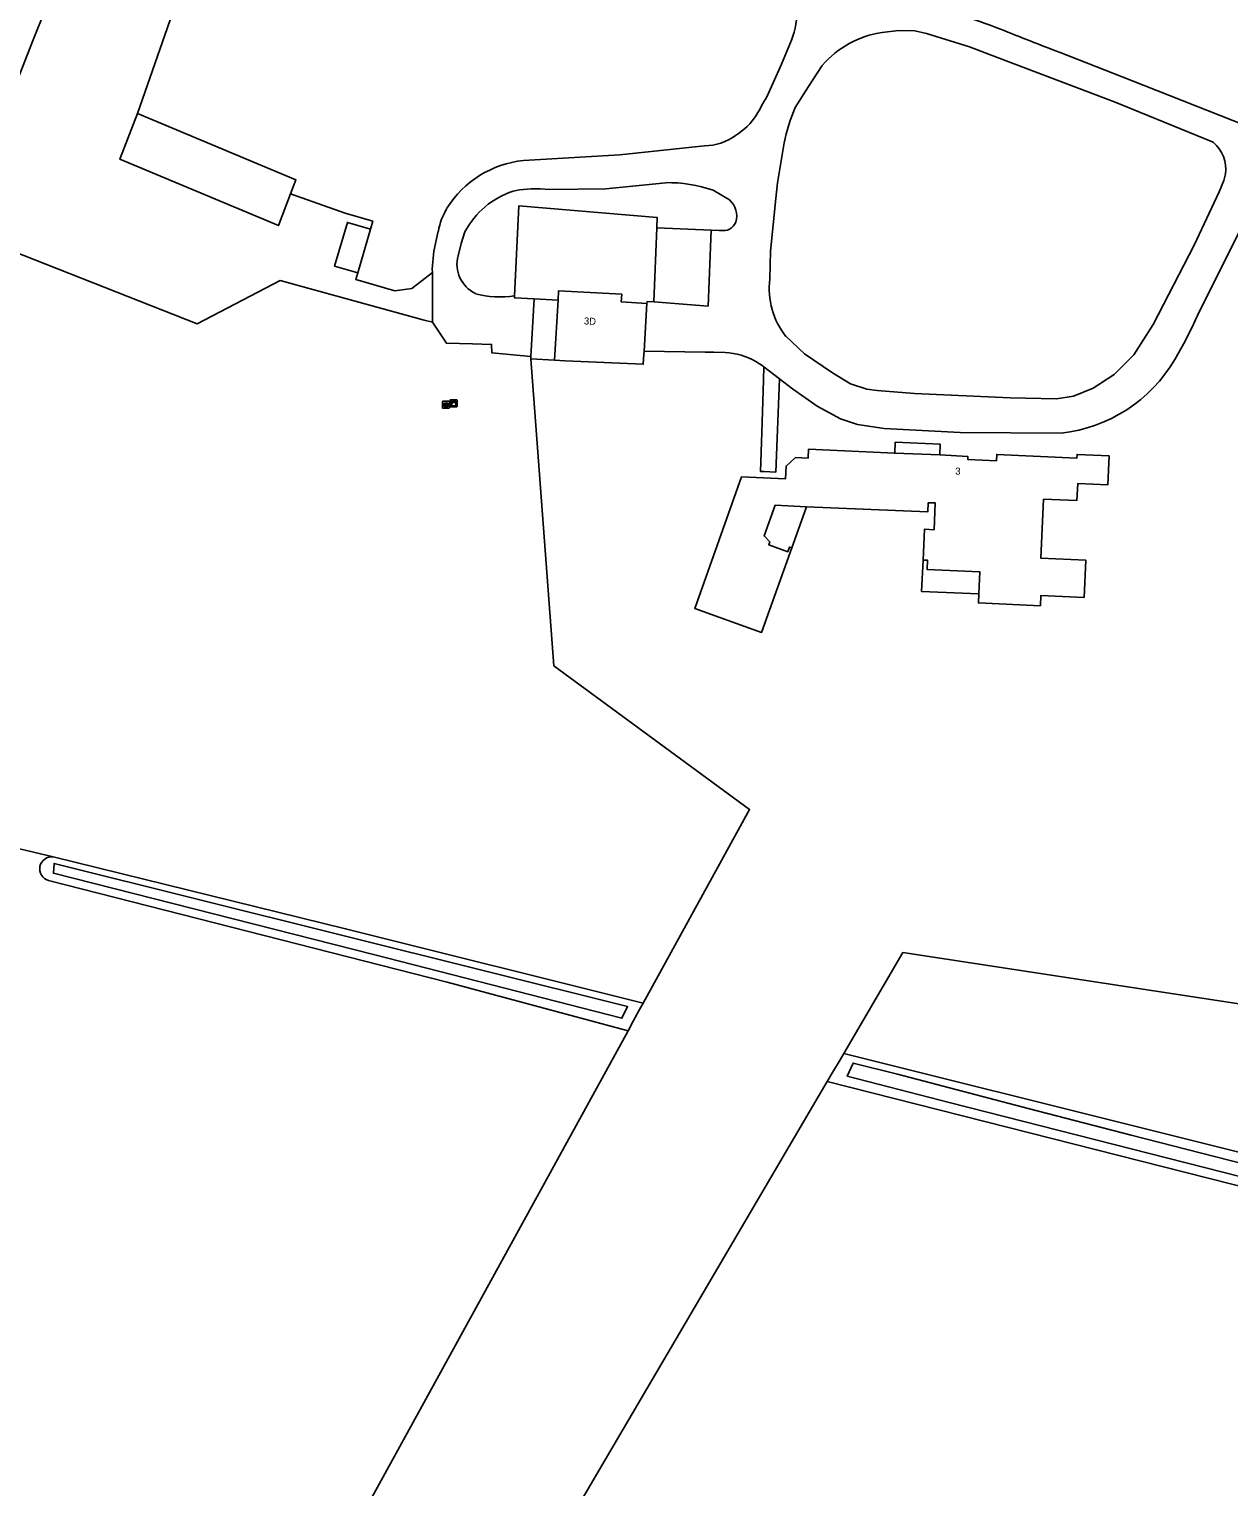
# Model space of a CAD drawing. Extents: x 156502 to 159075, y 384229 to 386100.
# Drawn here: x 158041.4 to 158212, y 384870.4 to 385077.7 of the extents above; entities that cross this region are included whole.
import ezdxf

# ---------------------------------------------------------------- set-up
doc = ezdxf.new("R2010")
doc.units = 0
for name, color, linetype in [('IMGEO_Erf', 7, 'Continuous'), ('IMGEO_Gemengd_bos', 7, 'Continuous'), ('IMGEO_Groenvoorziening', 7, 'Continuous'), ('IMGEO_Kast', 7, 'Continuous'), ('IMGEO_Oever', 7, 'Continuous'), ('IMGEO_Pand', 7, 'Continuous'), ('IMGEO_Pand_nummerreeks', 7, 'Continuous'), ('IMGEO_Pand_overbouw', 7, 'Continuous'), ('IMGEO_Parkeervlak_gesloten', 7, 'Continuous'), ('IMGEO_Rijbaan_lokaal_gesloten', 7, 'Continuous'), ('IMGEO_Rioolput', 7, 'Continuous'), ('IMGEO_Voetpad_onverhard', 7, 'Continuous'), ('IMGEO_Waterloop', 7, 'Continuous')]:
    doc.layers.add(name, color=color, linetype=linetype)

msp = doc.modelspace()

# ---------------------------------------------------------------- linework, layer by layer
at = {"layer": 'IMGEO_Erf'}
msp.add_lwpolyline([(158130.68, 385049.46), (158130.74, 385050.93), (158111.07, 385052.6), (158110.45, 385039.8), (158110.43, 385039.52), (158113.23, 385039.37), (158116.63, 385039.17), (158116.71, 385040.53), (158125.68, 385040.02), (158125.61, 385038.93), (158129.25, 385038.72), (158129.29, 385038.99), (158130.25, 385038.96)], close=True, dxfattribs=at)
at = {"layer": 'IMGEO_Gemengd_bos'}
for points in [[(158033.69, 385055.05), (158042.02, 385076.22), (158043.74, 385080.59), (158047.49, 385090.13), (158063.22, 385084.15), (158056.81, 385065.74), (158079.36, 385056.3), (158078.61, 385054.32), (158086.38, 385051.55), (158090.29, 385050.4), (158089.96, 385049.28), (158088.14, 385043.06), (158087.87, 385042.14), (158093.44, 385040.5), (158095.84, 385040.85), (158098.76, 385043.1), (158098.75, 385043.6), (158098.96, 385046.17), (158099.6, 385049.02)], [(158146.31, 385068.11), (158147.22, 385070.08), (158148.38, 385072.74), (158149.8, 385076.15)], [(158188.02, 385074.39), (158198.17, 385070.41), (158214.38, 385064.01), (158216.95, 385062.2), (158306.9, 385025.96), (158370.58, 385000), (158387.87, 384992.95)], [(158111.7, 385059.04), (158125.41, 385059.86), (158137.47, 385061.13)], [(158039.24, 384961.34), (158044.85, 384960), (158086.42, 384949.78), (158128.74, 384939.19), (158143.87, 384966.74), (158116.03, 384987.18), (158112.74, 385030.84), (158112.76, 385031.15), (158107.19, 385031.71), (158107.18, 385032.88), (158104.47, 385032.95), (158100.75, 385033.05), (158098.78, 385036.03), (158097.57, 385036.36), (158077.13, 385041.96), (158065.33, 385035.82), (158032.33, 385048.8)], [(158044.85, 384960), (158039.24, 384961.34)], [(158126.59, 384935.27), (158100.88, 384942.2), (158044.17, 384956.66)], [(158327.33, 384873.03), (158330.05, 384877.58), (158342.95, 384899.96), (158353.53, 384917.71), (158350.04, 384918.24), (158339.53, 384900.83), (158339.29, 384900.43), (158338.99, 384900.27), (158338.62, 384900.45), (158338.56, 384900.87), (158338.74, 384901.31), (158349.05, 384918.4), (158165.66, 384946.38), (158157.25, 384932.05), (158243.06, 384910.59), (158287.1, 384899.3), (158326.96, 384888.71), (158329.39, 384887.94)], [(158003.5, 384732.93), (158035.11, 384768.65), (158069.78, 384831.8), (158071.43, 384834.81), (158126.59, 384935.27)], [(158329.89, 384884.1), (158317.22, 384886.76), (158306.67, 384889.36), (158264.56, 384900.4), (158248.46, 384904.15), (158225.15, 384910.22), (158154.91, 384928.06), (158096.39, 384828.33), (158102.05, 384826.88), (158102.21, 384826.84), (158226.61, 384795.1), (158247.13, 384790.01), (158268.26, 384784.48)]]:
    msp.add_lwpolyline(points, dxfattribs=at)
for centre, radius, start, end in [((158139.92, 385080.19), 10.68, 337.7815, 3.4013), ((158159.52, 385028.6), 53.04, 67.851, 74.5481), ((158482.86, 385836.61), 817.26, 248.21267, 248.85308), ((158227.98, 385020.22), 94.67, 149.6116, 151.4029), ((158136.57, 385070.99), 9.92, 302.2145, 326.6471), ((158137.22, 385069.2), 8.08, 271.7889, 305.0575), ((158113.21, 385044.53), 14.59, 95.9317, 148.0469), ((158108.83, 385047.36), 9.37, 148.5861, 169.8084), ((158044.64, 384958.3), 1.71, 82.9909, 253.9412)]:
    msp.add_arc(centre, radius, start, end, dxfattribs=at)
at = {"layer": 'IMGEO_Groenvoorziening'}
for points in [[(158209.76, 385061.65), (158195.85, 385067.34), (158178.98, 385073.76), (158175.13, 385075.22), (158169.02, 385077.12), (158167.35, 385077.51), (158165.05, 385077.52), (158162.72, 385077.23)], [(158154.19, 385072.55), (158152.25, 385069.57), (158150.36, 385066.58)], [(158148.77, 385061.55), (158147.82, 385055.86), (158147.6, 385053.64), (158146.84, 385046.16), (158146.73, 385042.17)], [(158149.01, 385034.04), (158151.65, 385031.54), (158155.67, 385028.84), (158158.2, 385027.27), (158160.51, 385026.51), (158162.02, 385026.32), (158167.3, 385025.9), (158180.93, 385025.28), (158187.48, 385025.17), (158189.93, 385025.51), (158192.69, 385026.67), (158195.69, 385028.61), (158198.5, 385031.4), (158201.25, 385035.74), (158207.08, 385047.02), (158210.62, 385054.58), (158210.97, 385055.38), (158211.28, 385056.19), (158211.55, 385057.13)], [(158131.93, 385055.89), (158123.4, 385055.03), (158115.43, 385054.94), (158114.12, 385055.01), (158112.82, 385055.02), (158111.13, 385054.87), (158110.24, 385054.68)], [(158141, 385053.46), (158138.69, 385054.81)], [(158216.16, 385054.27), (158207.79, 385037.5), (158206.73, 385035.25), (158205.6, 385033.02), (158204.31, 385030.75)], [(158110.45, 385039.8), (158111.07, 385052.6), (158130.74, 385050.93), (158130.68, 385049.46), (158138.4, 385049.14), (158139.55, 385049.1), (158139.98, 385049.07), (158140.39, 385049.08)], [(158141.53, 385049.72), (158141.7, 385049.94), (158141.93, 385050.28)], [(158103.39, 385048.89), (158102.86, 385047.24), (158102.41, 385045.51)], [(158140.41, 385031.73), (158138.79, 385031.79), (158137.55, 385031.78), (158128.86, 385031.91), (158128.83, 385031.49), (158128.75, 385030.06), (158117.66, 385030.55), (158116.14, 385030.64), (158116.63, 385039.17), (158113.23, 385039.37), (158112.76, 385031.15), (158112.74, 385030.84), (158116.03, 384987.18), (158143.87, 384966.74), (158128.74, 384939.19), (158128.23, 384938.27), (158127.33, 384936.62), (158126.59, 384935.27), (158071.43, 384834.81), (158069.78, 384831.8), (158035.11, 384768.65), (158003.5, 384732.93)], [(158188.17, 385020.27), (158173.81, 385020.36), (158162.98, 385020.92), (158159.22, 385021.5), (158156.81, 385022.31), (158153.47, 385024.12), (158149.98, 385026.59), (158148.12, 385028.01), (158147.58, 385014.74), (158145.93, 385014.81), (158145.39, 385014.83), (158145.62, 385020.37), (158145.83, 385027.81), (158145.88, 385029.72), (158145.79, 385029.78), (158144.75, 385030.46)], [(158154.91, 384928.06), (158155.66, 384929.34), (158156.72, 384931.15), (158157.25, 384932.05), (158165.66, 384946.38), (158349.05, 384918.4), (158381.85, 384972.74), (158382.35, 384973.56)], [(158046.36, 384710.94), (158069.69, 384782.82), (158094.68, 384825.42), (158096.39, 384828.33), (158154.91, 384928.06)]]:
    msp.add_lwpolyline(points, dxfattribs=at)
msp.add_lwpolyline([(158136.07, 384995.32), (158142.71, 385014.04), (158148.97, 385013.78), (158149.06, 385015.59), (158150.38, 385016.79), (158152.17, 385016.73), (158152.23, 385017.97), (158164.51, 385017.4), (158170.93, 385017.17), (158174.9, 385016.94), (158174.88, 385016.54), (158178.95, 385016.35), (158179, 385017.25), (158190.4, 385016.71), (158190.43, 385017.25), (158194.97, 385017.04), (158194.78, 385012.9), (158190.51, 385013.1), (158190.4, 385010.69), (158185.67, 385010.9), (158185.29, 385002.48), (158191.66, 385002.19), (158191.42, 384996.88), (158185.27, 384997.16), (158185.21, 384995.71), (158176.4, 384996.11), (158176.46, 384997.39), (158176.6, 385000.53), (158169.12, 385000.87), (158169.18, 385002.19), (158168.53, 385002.22), (158168.73, 385006.59), (158170.1, 385006.53), (158170.27, 385010.34), (158169.27, 385010.38), (158169.21, 385009.09), (158151.97, 385009.79), (158147.49, 385010.01), (158145.92, 385005.66), (158146.74, 385004.83), (158146.58, 385004.38), (158149.29, 385003.41), (158149.53, 385004.07), (158149.88, 385003.95), (158145.57, 384991.92)], close=True, dxfattribs=at)
for centre, radius, start, end in [((158164.56, 385063.75), 13.61, 97.7663, 139.7016), ((158175.83, 385055.77), 27.67, 157.0109, 167.9586), ((158206.58, 385057.77), 5.01, 352.6092, 50.6216), ((158113.92, 385043.39), 11.88, 108.0707, 152.4223), ((158132.28, 385036.42), 19.48, 70.7938, 91.0277), ((158138.97, 385051.14), 3.08, 343.7315, 48.7723), ((158140.27, 385050.63), 1.56, 274.2809, 323.9475), ((158106.96, 385044.32), 4.7, 165.3599, 243.627), ((158157.73, 385040.87), 11.08, 173.2419, 218.0995), ((158108.37, 385053.01), 13.37, 254.8361, 278.9431), ((158140.01, 385022.39), 9.35, 59.5818, 87.549), ((158185.81, 385041.58), 21.44, 276.3262, 329.6768)]:
    msp.add_arc(centre, radius, start, end, dxfattribs=at)
at = {"layer": 'IMGEO_Kast'}
for p, q in [((158101.28, 385024.09), (158101.28, 385024.93)), ((158101.28, 385024.93), (158101.28, 385024.09)), ((158101.35, 385025.02), (158102.2, 385025.02)), ((158102.2, 385025.02), (158101.35, 385025.02)), ((158102.21, 385024.02), (158101.36, 385024.02)), ((158101.36, 385024.02), (158102.21, 385024.02)), ((158102.28, 385024.94), (158102.28, 385024.1)), ((158102.28, 385024.1), (158102.28, 385024.94))]:
    msp.add_line(p, q, dxfattribs=at)
for points in [[(158101.48, 385024.81), (158102.08, 385024.81), (158102.08, 385024.72), (158101.48, 385024.72), (158101.48, 385024.81)], [(158101.48, 385024.63), (158102.08, 385024.63), (158102.08, 385024.14), (158101.48, 385024.14), (158101.48, 385024.63)]]:
    msp.add_lwpolyline(points, dxfattribs=at)
msp.add_circle((158101.56, 385024.48), 0.0377, dxfattribs=at)
for centre, start, end in [((158101.36, 385024.94), 92.4484, 184.2845), ((158101.36, 385024.94), 92.4484, 184.2845), ((158101.36, 385024.1), 182.4484, 274.2845), ((158101.36, 385024.1), 182.4484, 274.2845), ((158102.2, 385024.94), 2.4484, 94.2845), ((158102.2, 385024.94), 2.4484, 94.2845), ((158102.2, 385024.1), 272.4484, 4.2845), ((158102.2, 385024.1), 272.4484, 4.2845)]:
    msp.add_arc(centre, 0.0779, start, end, dxfattribs=at)
at = {"layer": 'IMGEO_Oever'}
for points in [[(158086.42, 384949.78), (158044.85, 384960)], [(158044.17, 384956.66), (158100.88, 384942.2), (158126.59, 384935.27), (158127.33, 384936.62), (158128.23, 384938.27), (158128.74, 384939.19), (158086.42, 384949.78)], [(158329.39, 384887.94), (158326.96, 384888.71), (158287.1, 384899.3), (158243.06, 384910.59), (158157.25, 384932.05), (158156.72, 384931.15), (158155.66, 384929.34), (158154.91, 384928.06), (158225.15, 384910.22), (158248.46, 384904.15), (158264.56, 384900.4), (158306.67, 384889.36), (158317.22, 384886.76), (158329.89, 384884.1)]]:
    msp.add_lwpolyline(points, dxfattribs=at)
for points in [[(158126.51, 384938.7), (158125.72, 384937.04), (158090.38, 384946.13), (158044.88, 384957.66), (158044.97, 384959.08)], [(158329.1, 384885.67), (158328.78, 384885.46), (158328.16, 384885.41), (158326.59, 384885.73), (158318.91, 384887.72), (158172.42, 384925.02), (158157.74, 384928.8), (158158.6, 384930.67), (158164.9, 384929.1), (158183.49, 384924.23), (158198.1, 384920.41), (158328.29, 384887.11), (158328.86, 384886.59), (158329.18, 384886.17)]]:
    msp.add_lwpolyline(points, close=True, dxfattribs=at)
msp.add_arc((158044.64, 384958.3), 1.71, 82.9909, 253.9412, dxfattribs=at)
at = {"layer": 'IMGEO_Pand'}
for points in [[(158056.81, 385065.74), (158054.33, 385059.22), (158076.88, 385049.78), (158078.61, 385054.32), (158079.36, 385056.3)], [(158089.96, 385049.28), (158086.67, 385050.25), (158084.85, 385044.03), (158088.14, 385043.06)], [(158129.25, 385038.72), (158125.61, 385038.93), (158125.68, 385040.02), (158116.71, 385040.53), (158116.63, 385039.17), (158116.14, 385030.64), (158117.66, 385030.55), (158128.75, 385030.06), (158128.83, 385031.49), (158128.86, 385031.91)], [(158142.71, 385014.04), (158136.07, 384995.32), (158145.57, 384991.92), (158149.88, 385003.95), (158149.53, 385004.07), (158149.29, 385003.41), (158146.58, 385004.38), (158146.74, 385004.83), (158145.92, 385005.66), (158147.49, 385010.01), (158151.97, 385009.79), (158169.21, 385009.09), (158169.27, 385010.38), (158170.27, 385010.34), (158170.1, 385006.53), (158168.73, 385006.59), (158168.53, 385002.22), (158169.18, 385002.19), (158169.12, 385000.87), (158176.6, 385000.53), (158176.46, 384997.39), (158176.4, 384996.11), (158185.21, 384995.71), (158185.27, 384997.16), (158191.42, 384996.88), (158191.66, 385002.19), (158185.29, 385002.48), (158185.67, 385010.9), (158190.4, 385010.69), (158190.51, 385013.1), (158194.78, 385012.9), (158194.97, 385017.04), (158190.43, 385017.25), (158190.4, 385016.71), (158179, 385017.25), (158178.95, 385016.35), (158174.88, 385016.54), (158174.9, 385016.94), (158170.93, 385017.17), (158164.51, 385017.4), (158152.23, 385017.97), (158152.17, 385016.73), (158150.38, 385016.79), (158149.06, 385015.59), (158148.97, 385013.78)]]:
    msp.add_lwpolyline(points, close=True, dxfattribs=at)
at = {"layer": 'IMGEO_Pand_overbouw'}
for points in [[(158116.63, 385039.17), (158113.23, 385039.37), (158112.76, 385031.15), (158112.74, 385030.84), (158116.14, 385030.64)], [(158170.93, 385017.17), (158170.98, 385018.68), (158164.57, 385018.98), (158164.51, 385017.4)], [(158151.97, 385009.79), (158147.49, 385010.01), (158145.92, 385005.66), (158146.74, 385004.83), (158146.58, 385004.38), (158149.29, 385003.41), (158149.53, 385004.07), (158149.88, 385003.95)], [(158176.46, 384997.39), (158176.6, 385000.53), (158169.12, 385000.87), (158169.18, 385002.19), (158168.53, 385002.22), (158168.32, 384997.76)]]:
    msp.add_lwpolyline(points, close=True, dxfattribs=at)
at = {"layer": 'IMGEO_Parkeervlak_gesloten'}
msp.add_lwpolyline([(158138.4, 385049.14), (158130.68, 385049.46), (158130.25, 385038.96), (158137.96, 385038.33)], close=True, dxfattribs=at)
at = {"layer": 'IMGEO_Rijbaan_lokaal_gesloten'}
for points in [[(158032.33, 385048.8), (158065.33, 385035.82), (158077.13, 385041.96), (158097.57, 385036.36), (158098.78, 385036.03), (158098.76, 385041.03), (158098.76, 385043.1), (158095.84, 385040.85), (158093.44, 385040.5), (158087.87, 385042.14), (158088.14, 385043.06), (158084.85, 385044.03), (158086.67, 385050.25), (158089.96, 385049.28), (158090.29, 385050.4), (158086.38, 385051.55), (158078.61, 385054.32), (158076.88, 385049.78), (158054.33, 385059.22), (158056.81, 385065.74), (158063.22, 385084.15)], [(158043.74, 385080.59), (158042.02, 385076.22), (158033.69, 385055.05)], [(158162.72, 385077.23), (158165.05, 385077.52), (158167.35, 385077.51), (158169.02, 385077.12), (158175.13, 385075.22), (158178.98, 385073.76), (158195.85, 385067.34), (158209.76, 385061.65)], [(158149.8, 385076.15), (158148.38, 385072.74), (158147.22, 385070.08), (158146.31, 385068.11)], [(158387.87, 384992.95), (158370.58, 385000), (158306.9, 385025.96), (158216.95, 385062.2), (158214.38, 385064.01), (158198.17, 385070.41), (158188.02, 385074.39)], [(158150.36, 385066.58), (158152.25, 385069.57), (158154.19, 385072.55)], [(158137.47, 385061.13), (158125.41, 385059.86), (158111.7, 385059.04)], [(158146.73, 385042.17), (158146.84, 385046.16), (158147.6, 385053.64), (158147.82, 385055.86), (158148.77, 385061.55)], [(158211.55, 385057.13), (158211.28, 385056.19), (158210.97, 385055.38), (158210.62, 385054.58), (158207.08, 385047.02), (158201.25, 385035.74), (158198.5, 385031.4), (158195.69, 385028.61), (158192.69, 385026.67), (158189.93, 385025.51), (158187.48, 385025.17), (158180.93, 385025.28), (158167.3, 385025.9), (158162.02, 385026.32), (158160.51, 385026.51), (158158.2, 385027.27), (158155.67, 385028.84), (158151.65, 385031.54), (158149.01, 385034.04)], [(158110.24, 385054.68), (158111.13, 385054.87), (158112.82, 385055.02), (158114.12, 385055.01), (158115.43, 385054.94), (158123.4, 385055.03), (158131.93, 385055.89)], [(158138.69, 385054.81), (158141, 385053.46)], [(158204.31, 385030.75), (158205.6, 385033.02), (158206.73, 385035.25), (158207.79, 385037.5), (158216.16, 385054.27)], [(158141.93, 385050.28), (158141.7, 385049.94), (158141.53, 385049.72)], [(158099.6, 385049.02), (158098.96, 385046.17), (158098.75, 385043.6), (158098.76, 385043.1), (158098.76, 385041.03), (158098.78, 385036.03), (158100.75, 385033.05), (158104.47, 385032.95), (158107.18, 385032.88), (158107.19, 385031.71), (158112.76, 385031.15), (158113.23, 385039.37), (158110.43, 385039.52), (158110.45, 385039.8)], [(158102.41, 385045.51), (158102.86, 385047.24), (158103.39, 385048.89)], [(158140.39, 385049.08), (158139.98, 385049.07), (158139.55, 385049.1), (158138.4, 385049.14), (158137.96, 385038.33), (158130.25, 385038.96), (158129.29, 385038.99), (158129.25, 385038.72), (158128.86, 385031.91), (158137.55, 385031.78), (158138.79, 385031.79), (158140.41, 385031.73)], [(158144.75, 385030.46), (158145.79, 385029.78), (158145.88, 385029.72), (158148.12, 385028.01), (158149.98, 385026.59), (158153.47, 385024.12), (158156.81, 385022.31), (158159.22, 385021.5), (158162.98, 385020.92), (158173.81, 385020.36), (158188.17, 385020.27)]]:
    msp.add_lwpolyline(points, dxfattribs=at)
for centre, radius, start, end in [((158139.92, 385080.19), 10.68, 337.7815, 3.4013), ((158159.52, 385028.6), 53.04, 67.851, 74.5481), ((158164.56, 385063.75), 13.61, 97.7663, 139.7016), ((158482.86, 385836.61), 817.26, 248.21267, 248.85308), ((158227.98, 385020.22), 94.67, 149.6116, 151.4029), ((158136.57, 385070.99), 9.92, 302.2145, 326.6471), ((158175.83, 385055.77), 27.67, 157.0109, 167.9586), ((158137.22, 385069.2), 8.08, 271.7889, 305.0575), ((158206.58, 385057.77), 5.01, 352.6092, 50.6216), ((158113.21, 385044.53), 14.59, 95.9317, 148.0469), ((158113.92, 385043.39), 11.88, 108.0707, 152.4223), ((158132.28, 385036.42), 19.48, 70.7938, 91.0277), ((158108.83, 385047.36), 9.37, 148.5861, 169.8084), ((158138.97, 385051.14), 3.08, 343.7315, 48.7723), ((158140.27, 385050.63), 1.56, 274.2809, 323.9475), ((158106.96, 385044.32), 4.7, 165.3599, 243.627), ((158157.73, 385040.87), 11.08, 173.2419, 218.0995), ((158108.37, 385053.01), 13.37, 254.8361, 278.9431), ((158140.01, 385022.39), 9.35, 59.5818, 87.549), ((158185.81, 385041.58), 21.44, 276.3262, 329.6768)]:
    msp.add_arc(centre, radius, start, end, dxfattribs=at)
at = {"layer": 'IMGEO_Rioolput'}
for p, q in [((158100.19, 385023.88), (158100.19, 385024.73)), ((158100.26, 385024.81), (158101.11, 385024.81)), ((158101.11, 385023.81), (158100.26, 385023.81)), ((158100.45, 385024.3), (158100.45, 385024.31)), ((158100.49, 385024.35), (158100.89, 385024.35)), ((158100.88, 385024.26), (158100.49, 385024.26)), ((158100.7, 385024.03), (158100.67, 385024.03)), ((158100.68, 385024.59), (158100.7, 385024.59)), ((158100.93, 385024.31), (158100.93, 385024.3)), ((158101.19, 385024.73), (158101.19, 385023.88))]:
    msp.add_line(p, q, dxfattribs=at)
for points in [[(158100.19, 385023.88), (158100.19, 385024.73)], [(158100.26, 385024.81), (158101.11, 385024.81)], [(158101.11, 385023.81), (158100.26, 385023.81)], [(158101.19, 385024.73), (158101.19, 385023.88)]]:
    msp.add_lwpolyline(points, dxfattribs=at)
for centre, radius, start, end in [((158100.26, 385024.73), 0.0765, 91.552, 178.448), ((158100.26, 385024.73), 0.0765, 91.552, 178.448), ((158100.26, 385023.88), 0.0765, 181.552, 268.448), ((158100.26, 385023.88), 0.0765, 181.552, 268.448), ((158100.49, 385024.31), 0.0403, 85.8775, 175.7526), ((158100.48, 385024.3), 0.0366, 178.938, 274.7102), ((158100.89, 385024.31), 0.043, 264.8664, 352.4533), ((158100.89, 385024.31), 0.0386, 1.7309, 96.639), ((158101.11, 385024.73), 0.0765, 1.552, 88.448), ((158101.11, 385024.73), 0.0765, 1.552, 88.448), ((158101.11, 385023.88), 0.0765, 271.552, 358.448), ((158101.11, 385023.88), 0.0765, 271.552, 358.448)]:
    msp.add_arc(centre, radius, start, end, dxfattribs=at)
for centre, major_axis, ratio, start_param, end_param in [((158100.67, 385024.31), (-0.387, 0.002), 0.722429, 4.712389, 7.853982), ((158100.7, 385024.31), (-0.39, 0.002), 0.717154, 1.570796, 4.712389)]:
    msp.add_ellipse(centre, major_axis=major_axis, ratio=ratio, start_param=start_param, end_param=end_param, dxfattribs=at)
at = {"layer": 'IMGEO_Voetpad_onverhard'}
msp.add_lwpolyline([(158148.12, 385028.01), (158145.88, 385029.72), (158145.83, 385027.81), (158145.62, 385020.37), (158145.39, 385014.83), (158145.93, 385014.81), (158147.58, 385014.74)], close=True, dxfattribs=at)
at = {"layer": 'IMGEO_Waterloop'}
for points in [[(158044.97, 384959.08), (158044.88, 384957.66), (158090.38, 384946.13), (158125.72, 384937.04), (158126.51, 384938.7)], [(158183.49, 384924.23), (158164.9, 384929.1), (158158.6, 384930.67), (158157.74, 384928.8), (158172.42, 384925.02), (158318.91, 384887.72), (158326.59, 384885.73), (158328.16, 384885.41), (158328.78, 384885.46), (158329.1, 384885.67), (158329.18, 384886.17), (158328.86, 384886.59), (158328.29, 384887.11), (158198.1, 384920.41)]]:
    msp.add_lwpolyline(points, close=True, dxfattribs=at)

# ---------------------------------------------------------------- texts
at = {"layer": 'IMGEO_Pand_nummerreeks'}
for s, rotation, p in [('3D', 357.1868, (158120.29, 385035.74)), ('3', 358.2371, (158173.1, 385014.38))]:
    msp.add_text(s, height=1, rotation=rotation, dxfattribs=at).set_placement(p)

doc.saveas('drawing.dxf')
